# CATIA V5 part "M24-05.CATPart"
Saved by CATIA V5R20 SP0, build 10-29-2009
Part number: M24-05
Revision: ANY
Definition: UNKNOWN
Nomenclature: M24-05
Source: Unknown
Bounding box of the stored display mesh (mm): x -40 to 40, y -40 to 40, z 0 to 20
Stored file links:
  C:\Users\Utente\Desktop\IO LAVORO\3D X SITO CF\X 3D SITO CF 27-09-2020\740T\740T-24\M24-05.CATPart
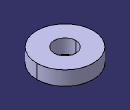
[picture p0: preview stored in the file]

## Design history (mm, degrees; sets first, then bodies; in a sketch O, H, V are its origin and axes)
Body1 "NONE" (main body)
  Solid1: solid without history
